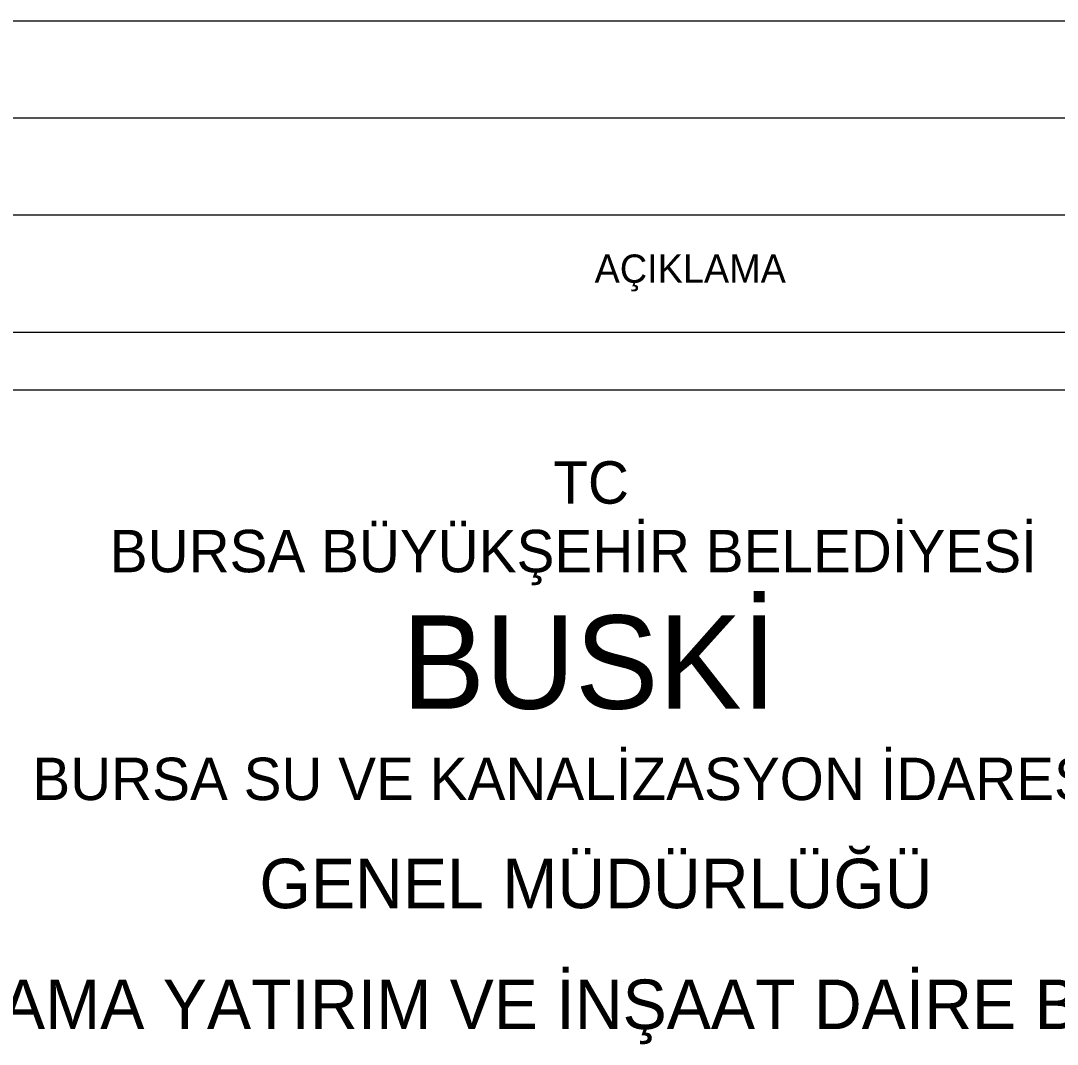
# Model space of a CAD drawing. Extents: x -10 to 1145, y -10 to 821.
# Drawn here: x 1008.8 to 1082.1, y 206.9 to 279.2 of the extents above; entities that cross this region are included whole.
import ezdxf

# ---------------------------------------------------------------- set-up
doc = ezdxf.new("R2010")
doc.units = 0
for name, color, linetype in [('Level 20', 7, 'Continuous'), ('Level 6', 7, 'Continuous'), ('Level 7', 7, 'Continuous')]:
    doc.layers.add(name, color=color, linetype=linetype)

msp = doc.modelspace()

# ---------------------------------------------------------------- linework, layer by layer
at = {"layer": 'Level 6'}
for p, q in [((967.025, 279.244), (1135, 279.244)), ((967.025, 279.244), (1135, 279.244)), ((967.025, 279.244), (1135, 279.244)), ((967.025, 279.244), (1135, 279.244)), ((970.154, 279.244), (1131.871, 279.244)), ((970.154, 279.244), (1131.871, 279.244)), ((970.154, 279.244), (1131.871, 279.244)), ((970.154, 279.244), (1131.871, 279.244)), ((970.154, 279.244), (1131.871, 279.244)), ((970.154, 279.244), (1131.871, 279.244)), ((970.154, 279.244), (1131.871, 279.244)), ((970.154, 279.244), (1131.871, 279.244)), ((967.025, 272.38), (1135, 272.38)), ((967.025, 272.38), (1135, 272.38)), ((967.025, 272.38), (1135, 272.38)), ((967.025, 272.38), (1135, 272.38)), ((967.025, 265.521), (1135, 265.521)), ((967.025, 265.521), (1135, 265.521)), ((967.025, 265.521), (1135, 265.521)), ((967.025, 265.521), (1135, 265.521)), ((967.025, 257.229), (1135, 257.229)), ((967.025, 257.229), (1135, 257.229)), ((967.025, 257.229), (1135, 257.229)), ((967.025, 257.229), (1135, 257.229)), ((967.025, 253.135), (1135, 253.135)), ((967.025, 253.135), (1135, 253.135)), ((967.025, 253.135), (1135, 253.135)), ((967.025, 253.135), (1135, 253.135))]:
    msp.add_line(p, q, dxfattribs=at)

# ---------------------------------------------------------------- texts
at = {"layer": 'Level 20'}
for s, p in [('GENEL MÜDÜRLÜĞÜ', (1025.69, 216.483)), ('PLANLAMA YATIRIM VE İNŞAAT DAİRE BAŞKANLIĞI', (992.587, 207.938))]:
    msp.add_text(s, height=3.5, dxfattribs=at).set_placement(p)
at = {"layer": 'Level 7'}
for s, height, p in [('AÇIKLAMA', 2, (1049.385, 260.712)), ('TC', 3, (1046.464, 245.089)), ('BURSA BÜYÜKŞEHİR BELEDİYESİ', 3, (1015.112, 240.24)), ('BUSKİ', 6.6017, (1035.749, 230.587)), ('BURSA SU VE KANALİZASYON İDARESİ', 3, (1009.637, 224.129))]:
    msp.add_text(s, height=height, dxfattribs=at).set_placement(p)

doc.saveas('drawing.dxf')
